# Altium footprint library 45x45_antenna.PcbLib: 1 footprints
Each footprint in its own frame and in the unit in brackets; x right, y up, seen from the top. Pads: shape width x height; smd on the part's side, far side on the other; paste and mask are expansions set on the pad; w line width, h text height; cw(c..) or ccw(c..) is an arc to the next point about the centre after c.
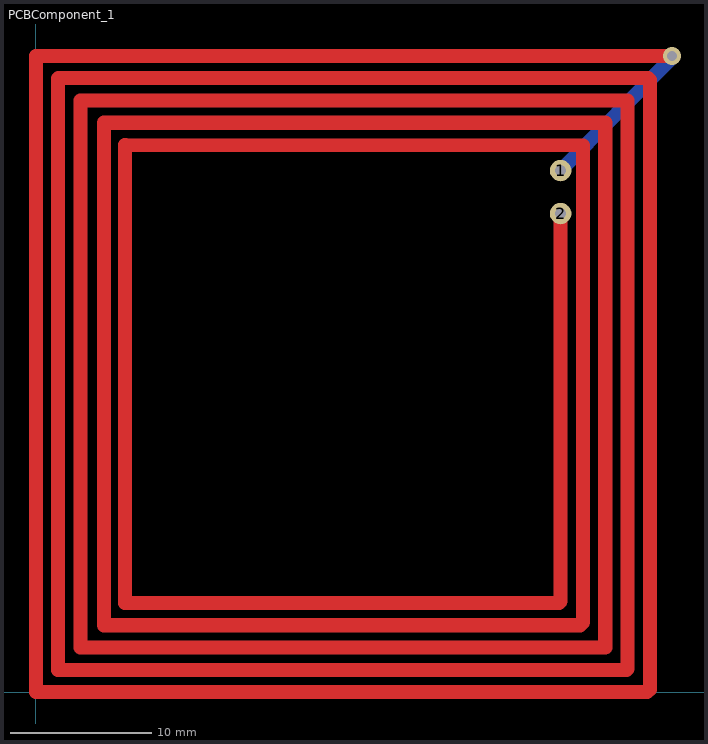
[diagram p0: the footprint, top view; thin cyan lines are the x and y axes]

## PCBComponent_1 [mil]
pads (2):
  round 60 hole 30: 1(1463.78,1455) 2(1463.78,1335)
via 1775,1775 diameter 50 hole 28
Top Layer:
  lines w10: 1775,1770 1775,1775 1775,1770
  lines w39.37: 0,0 1705,0 1712.6,7.6 1712.6,1707.4 1707.2,1712.8 62.8,1712.8 62.2,1712.2 62.2,62.2 1647.2,62.2 1650.39,65.39 1650.39,1650 ; 0,5 0,1775 1775,1775 ; 124.41,1650.59 124.41,124.41 1587.6,124.41 1588.19,125 1588.19,1585 ; 125,1650.59 1650.39,1650.59 ; 190,186.61 1517.6,186.61 1525.98,195 1525.98,1525 250,1526.35 ; 190,190 190,1588.39 1588.19,1588.39 ; 248.82,248.82 1458.82,248.82 1463.78,253.78 1463.78,1335 ; 248.82,250 248.82,1526.35
Bottom Layer:
  lines w39.37: 1463.78,1455 1775,1770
